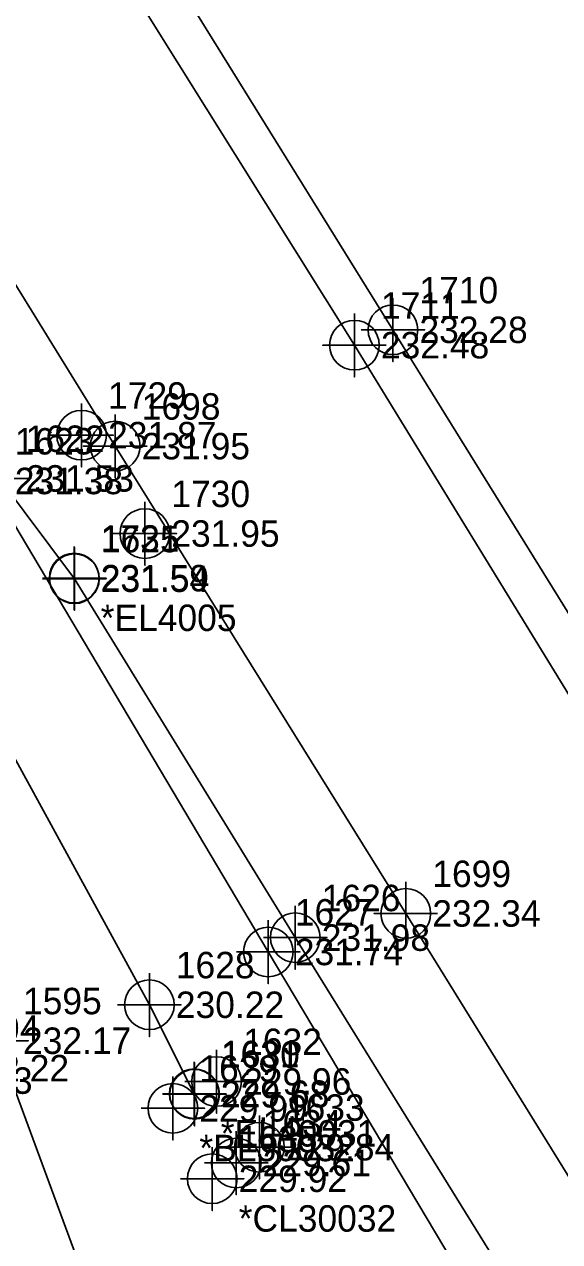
# Model space of a CAD drawing. Extents: x 2130962 to 2131465, y 643052 to 644206.
# Drawn here: x 2131153.9 to 2131204.4, y 643894.5 to 644009.5 of the extents above; entities that cross this region are included whole.
import ezdxf

# ---------------------------------------------------------------- set-up
doc = ezdxf.new("R2010")
doc.units = 0
for name, color, linetype in [('Exist DTM Breakline', 7, 'Continuous'), ('Exist DTM Breakline Cogo Comment', 7, 'Continuous'), ('Exist DTM Breakline Cogo Elevation', 7, 'Continuous'), ('Exist DTM Breakline Cogo Number', 7, 'Continuous'), ('Exist DTM Breakline Cogo Point CELL', 7, 'Continuous'), ('Exist DTM Drainline', 7, 'Continuous'), ('Exist DTM Drainline Cogo Comment', 7, 'Continuous'), ('Exist DTM Drainline Cogo Elevation', 7, 'Continuous'), ('Exist DTM Drainline Cogo Number', 7, 'Continuous'), ('Exist DTM Drainline Cogo Point CELL', 7, 'Continuous'), ('Exist Roads EOP', 7, 'Continuous'), ('Exist Roads EOP Cogo Elevation', 7, 'Continuous'), ('Exist Roads EOP Cogo Number', 7, 'Continuous'), ('Exist Roads EOP Other Cogo Comment', 7, 'Continuous'), ('Exist Roads EOP Other Cogo Elevation', 7, 'Continuous'), ('Exist Roads EOP Other Cogo Number', 7, 'Continuous'), ('Exist Roads EOP Other Cogo Point CELL', 7, 'Continuous'), ('Exist Roads EOT', 7, 'Continuous'), ('Exist Roads EOT Cogo Elevation', 7, 'Continuous'), ('Exist Roads EOT Cogo Number', 7, 'Continuous'), ('Exist Roads EOT Cogo Point CELL', 7, 'Continuous')]:
    doc.layers.add(name, color=color, linetype=linetype)

msp = doc.modelspace()

# ---------------------------------------------------------------- linework, layer by layer
at = {"layer": 'Exist DTM Breakline'}
for points in [[(2131266.3306, 643269.372), (2131264.0776, 643319.4437), (2131258.8396, 643369.5498), (2131255.3671, 643419.5794), (2131249.6414, 643469.556), (2131244.7652, 643520.0623), (2131238.8778, 643569.4077), (2131228.6495, 643620.6699), (2131219.85, 643669.4823), (2131206.9682, 643717.8453), (2131195.8132, 643768.1497), (2131183.2404, 643816.8151), (2131169.0496, 643865.1461), (2131151.2314, 643913.4424), (2131130.7295, 643958.9736), (2131122.7411, 643983.0115)], [(2131150.4586, 643966.3443), (2131176.896, 643921.8304), (2131203.4733, 643877.1362), (2131230.3046, 643833.1199)]]:
    msp.add_lwpolyline(points, dxfattribs=at)
at = {"layer": 'Exist DTM Breakline Cogo Point CELL'}
for points in [[(2131159.268, 643973.6708), (2131159.268, 643967.6708), (2131159.268, 643970.6708), (2131162.268, 643970.6708), (2131156.268, 643970.6708)], [(2131165.2384, 643964.3754), (2131165.2384, 643958.3754), (2131165.2384, 643961.3754), (2131168.2384, 643961.3754), (2131162.2384, 643961.3754)], [(2131158.5663, 643960.1621), (2131158.5663, 643954.1621), (2131158.5663, 643957.1621), (2131161.5663, 643957.1621), (2131155.5663, 643957.1621)], [(2131176.896, 643924.8304), (2131176.896, 643918.8304), (2131176.896, 643921.8304), (2131179.896, 643921.8304), (2131173.896, 643921.8304)], [(2131151.2314, 643916.4424), (2131151.2314, 643910.4424), (2131151.2314, 643913.4424), (2131154.2314, 643913.4424), (2131148.2314, 643913.4424)]]:
    msp.add_lwpolyline(points, dxfattribs=at)
for centre in [(2131159.268, 643970.6708), (2131165.2384, 643961.3754), (2131158.5663, 643957.1621), (2131176.896, 643921.8304)]:
    msp.add_circle(centre, 2.344, dxfattribs=at)
at = {"layer": 'Exist DTM Drainline'}
msp.add_lwpolyline([(2131124.9344, 643988.9242), (2131140.7825, 643962.3724), (2131165.6632, 643916.8402), (2131169.9073, 643908.436)], dxfattribs=at)
at = {"layer": 'Exist DTM Drainline Cogo Point CELL'}
for points in [[(2131165.6632, 643919.8402), (2131165.6632, 643913.8402), (2131165.6632, 643916.8402), (2131168.6632, 643916.8402), (2131162.6632, 643916.8402)], [(2131169.9073, 643911.436), (2131169.9073, 643905.436), (2131169.9073, 643908.436), (2131172.9073, 643908.436), (2131166.9073, 643908.436)]]:
    msp.add_lwpolyline(points, dxfattribs=at)
for centre in [(2131165.6632, 643916.8402), (2131169.9073, 643908.436)]:
    msp.add_circle(centre, 2.344, dxfattribs=at)
at = {"layer": 'Exist Roads EOP'}
for points in [[(2131269.8281, 643849.5438), (2131245.2333, 643889.3452), (2131216.1751, 643936.1301), (2131188.6585, 643980.6301), (2131160.5575, 644026.0233), (2131133.7706, 644069.3844), (2131106.5621, 644113.2921), (2131078.4587, 644158.6941), (2131052.1516, 644201.1049)], [(2131124.9979, 644001.4036), (2131151.4846, 643966.5856), (2131158.5905, 643957.1022), (2131179.4402, 643923.1833), (2131206.9257, 643878.7542), (2131233.5521, 643835.7453)]]:
    msp.add_lwpolyline(points, dxfattribs=at)
msp.add_spline([(2131166.2495, 643216.6951), (2131171.8131, 643218.7244), (2131182.3713, 643223.9726), (2131191.8117, 643231.1489), (2131200.5013, 643239.6993), (2131208.8071, 643249.0697), (2131216.0672, 643259.0032), (2131218.7188, 643264.347), (2131220.5363, 643270.0958), (2131222.8445, 643282.0077), (2131224.3583, 643293.9245), (2131224.8763, 643317.7904), (2131222.0632, 643367.6716), (2131218.5448, 643416.8114), (2131214.3187, 643466.3462), (2131209.1735, 643515.6666), (2131202.7939, 643565.1545), (2131195.0475, 643613.9937), (2131186.4014, 643662.4763), (2131176.0113, 643711.405), (2131164.6154, 643759.8896), (2131151.874, 643807.8526), (2131137.8554, 643855.4065), (2131122.5733, 643902.8574), (2131105.9622, 643949.4862), (2131091.5349, 643988.0437)], degree=3, dxfattribs=at)
at = {"layer": 'Exist Roads EOP Other Cogo Point CELL'}
for points in [[(2131188.6585, 643983.6301), (2131188.6585, 643977.6301), (2131188.6585, 643980.6301), (2131191.6585, 643980.6301), (2131185.6585, 643980.6301)], [(2131151.4846, 643969.5856), (2131151.4846, 643963.5856), (2131151.4846, 643966.5856), (2131154.4846, 643966.5856), (2131148.4846, 643966.5856)], [(2131158.5905, 643960.1022), (2131158.5905, 643954.1022), (2131158.5905, 643957.1022), (2131161.5905, 643957.1022), (2131155.5905, 643957.1022)], [(2131179.4402, 643926.1833), (2131179.4402, 643920.1833), (2131179.4402, 643923.1833), (2131182.4402, 643923.1833), (2131176.4402, 643923.1833)], [(2131172.0139, 643912.5898), (2131172.0139, 643906.5898), (2131172.0139, 643909.5898), (2131175.0139, 643909.5898), (2131169.0139, 643909.5898)], [(2131169.9398, 643911.3834), (2131169.9398, 643905.3834), (2131169.9398, 643908.3834), (2131172.9398, 643908.3834), (2131166.9398, 643908.3834)], [(2131167.8843, 643910.0536), (2131167.8843, 643904.0536), (2131167.8843, 643907.0536), (2131170.8843, 643907.0536), (2131164.8843, 643907.0536)], [(2131176.0526, 643906.377), (2131176.0526, 643900.377), (2131176.0526, 643903.377), (2131179.0526, 643903.377), (2131173.0526, 643903.377)], [(2131173.8631, 643904.8869), (2131173.8631, 643898.8869), (2131173.8631, 643901.8869), (2131176.8631, 643901.8869), (2131170.8631, 643901.8869)], [(2131171.5984, 643903.3961), (2131171.5984, 643897.3961), (2131171.5984, 643900.3961), (2131174.5984, 643900.3961), (2131168.5984, 643900.3961)]]:
    msp.add_lwpolyline(points, dxfattribs=at)
for centre in [(2131188.6585, 643980.6301), (2131158.5905, 643957.1022), (2131179.4402, 643923.1833), (2131172.0139, 643909.5898), (2131169.9398, 643908.3834), (2131167.8843, 643907.0536), (2131176.0526, 643903.377), (2131173.8631, 643901.8869), (2131171.5984, 643900.3961)]:
    msp.add_circle(centre, 2.344, dxfattribs=at)
at = {"layer": 'Exist Roads EOT'}
for points in [[(2131266.2139, 643847.7337), (2131241.6557, 643887.3896), (2131212.415, 643934.4728), (2131185.0265, 643979.1763), (2131157.0131, 644024.017), (2131130.1473, 644067.7247), (2131102.8992, 644111.8313), (2131074.9921, 644156.7275), (2131048.5158, 644199.6357)], [(2131027.1782, 644188.3908), (2131054.4288, 644144.4752), (2131080.5567, 644102.0812), (2131108.007, 644057.7457), (2131134.6373, 644014.7205), (2131162.4421, 643969.638), (2131189.8746, 643925.4695), (2131217.6277, 643880.5724), (2131241.9317, 643841.1922)]]:
    msp.add_lwpolyline(points, dxfattribs=at)
msp.add_spline([(2131166.718, 643215.2083), (2131172.3866, 643217.1804), (2131211.4056, 643247.1499), (2131223.758, 643268.7314), (2131228.3848, 643317.935), (2131225.533, 643367.8628), (2131222.2486, 643417.1873), (2131217.9619, 643466.6275), (2131212.8794, 643516.2377), (2131206.5633, 643565.5764), (2131198.9021, 643614.6757), (2131189.6851, 643663.4055), (2131179.3985, 643712.1311), (2131168.3085, 643760.7185), (2131155.755, 643808.9129), (2131141.6748, 643856.5528), (2131126.5354, 643904.2758), (2131110.3559, 643951.0191), (2131092.4533, 643998.1348), (2131073.722, 644043.631), (2131053.1654, 644089.359), (2131032.0052, 644134.0908), (2131009.0644, 644179.3802)], degree=3, dxfattribs=at)
at = {"layer": 'Exist Roads EOT Cogo Point CELL'}
for points in [[(2131185.0265, 643982.1763), (2131185.0265, 643976.1763), (2131185.0265, 643979.1763), (2131182.0265, 643979.1763), (2131188.0265, 643979.1763)], [(2131162.4421, 643972.638), (2131162.4421, 643966.638), (2131162.4421, 643969.638), (2131159.4421, 643969.638), (2131165.4421, 643969.638)], [(2131189.8746, 643928.4695), (2131189.8746, 643922.4695), (2131189.8746, 643925.4695), (2131186.8746, 643925.4695), (2131192.8746, 643925.4695)]]:
    msp.add_lwpolyline(points, dxfattribs=at)
for centre in [(2131185.0265, 643979.1763), (2131162.4421, 643969.638), (2131189.8746, 643925.4695)]:
    msp.add_circle(centre, 2.344, dxfattribs=at)

# ---------------------------------------------------------------- texts
at = {"layer": 'Exist DTM Breakline Cogo Comment'}
msp.add_text('*EL4005', height=2.5, dxfattribs=at).set_placement((2131161.0663, 643952.1621))
at = {"layer": 'Exist DTM Breakline Cogo Elevation'}
for s, p in [('231.87', (2131161.768, 643969.4208)), ('231.38', (2131152.9586, 643965.0943)), ('231.95', (2131167.7384, 643960.1254)), ('231.59', (2131161.0663, 643955.9121)), ('231.74', (2131179.396, 643920.5804)), ('232.17', (2131153.7314, 643912.1924))]:
    msp.add_text(s, height=2.5, dxfattribs=at).set_placement(p)
at = {"layer": 'Exist DTM Breakline Cogo Number'}
for s, p in [('1729', (2131161.768, 643973.1708)), ('1623', (2131152.9586, 643968.8443)), ('1730', (2131167.7384, 643963.8754)), ('1731', (2131161.0663, 643959.6621)), ('1627', (2131179.396, 643924.3304)), ('1595', (2131153.7314, 643915.9424))]:
    msp.add_text(s, height=2.5, dxfattribs=at).set_placement(p)
at = {"layer": 'Exist DTM Drainline Cogo Comment'}
msp.add_text('*EL40031', height=2.5, dxfattribs=at).set_placement((2131172.4073, 643903.436))
at = {"layer": 'Exist DTM Drainline Cogo Elevation'}
for s, p in [('230.22', (2131168.1632, 643915.5902)), ('229.68', (2131172.4073, 643907.186))]:
    msp.add_text(s, height=2.5, dxfattribs=at).set_placement(p)
at = {"layer": 'Exist DTM Drainline Cogo Number'}
for s, p in [('1628', (2131168.1632, 643919.3402)), ('1631', (2131172.4073, 643910.936))]:
    msp.add_text(s, height=2.5, dxfattribs=at).set_placement(p)
at = {"layer": 'Exist Roads EOP Cogo Elevation'}
msp.add_text('232.22', height=2.5, dxfattribs=at).set_placement((2131147.8604, 643909.5986))
at = {"layer": 'Exist Roads EOP Cogo Number'}
msp.add_text('1594', height=2.5, dxfattribs=at).set_placement((2131147.8604, 643913.3486))
at = {"layer": 'Exist Roads EOP Other Cogo Comment'}
for s, p in [('*BL30032', (2131170.3843, 643902.0536)), ('*CL30032', (2131174.0984, 643895.3961))]:
    msp.add_text(s, height=2.5, dxfattribs=at).set_placement(p)
at = {"layer": 'Exist Roads EOP Other Cogo Elevation'}
for s, p in [('232.28', (2131191.1585, 643979.3801)), ('231.53', (2131153.9846, 643965.3356)), ('231.54', (2131161.0905, 643955.8522)), ('231.98', (2131181.9402, 643921.9333)), ('229.96', (2131174.5139, 643908.3398)), ('229.68', (2131172.4398, 643907.1334)), ('229.99', (2131170.3843, 643905.8036)), ('229.84', (2131178.5526, 643902.127)), ('229.61', (2131176.3631, 643900.6369)), ('229.92', (2131174.0984, 643899.1461))]:
    msp.add_text(s, height=2.5, dxfattribs=at).set_placement(p)
at = {"layer": 'Exist Roads EOP Other Cogo Number'}
for s, p in [('1710', (2131191.1585, 643983.1301)), ('1622', (2131153.9846, 643969.0856)), ('1625', (2131161.0905, 643959.6022)), ('1626', (2131181.9402, 643925.6833)), ('1632', (2131174.5139, 643912.0898)), ('1630', (2131172.4398, 643910.8834)), ('1629', (2131170.3843, 643909.5536)), ('1633', (2131178.5526, 643905.877)), ('1634', (2131176.3631, 643904.3869)), ('1635', (2131174.0984, 643902.8961))]:
    msp.add_text(s, height=2.5, dxfattribs=at).set_placement(p)
at = {"layer": 'Exist Roads EOT Cogo Elevation'}
for s, p in [('232.48', (2131187.5265, 643977.9263)), ('231.95', (2131164.9421, 643968.388)), ('232.34', (2131192.3746, 643924.2195)), ('232.23', (2131144.4103, 643908.4222))]:
    msp.add_text(s, height=2.5, dxfattribs=at).set_placement(p)
at = {"layer": 'Exist Roads EOT Cogo Number'}
for s, p in [('1711', (2131187.5265, 643981.6763)), ('1698', (2131164.9421, 643972.138)), ('1699', (2131192.3746, 643927.9695))]:
    msp.add_text(s, height=2.5, dxfattribs=at).set_placement(p)

doc.saveas('drawing.dxf')
